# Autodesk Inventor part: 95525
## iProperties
Author: Administrator
Shininess: 64.0
Angle Display Precision: 2
Document Length Units: 11272
Document Angle Units: 11286
Document Time Units: 11279
Document Mass Units: 11290
Document Length Units Precision: 3
Document Angle Units Precision: 2
Compacted: True
PropertySet Name: _Private Model Information
Created: 2002-04
Part Number: 95525
Material: Stainless Steel, 440C
Document SubType Name: Modeling
Designer: Administrator
Control State: 0
Master: False
Checked Out: False
PropertySet Name: Design Tracking Control
Density: 0.0
Volumn: 0.0
Area: 0.0
PropertySet Name: Model Information
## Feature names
1. Revolution1
